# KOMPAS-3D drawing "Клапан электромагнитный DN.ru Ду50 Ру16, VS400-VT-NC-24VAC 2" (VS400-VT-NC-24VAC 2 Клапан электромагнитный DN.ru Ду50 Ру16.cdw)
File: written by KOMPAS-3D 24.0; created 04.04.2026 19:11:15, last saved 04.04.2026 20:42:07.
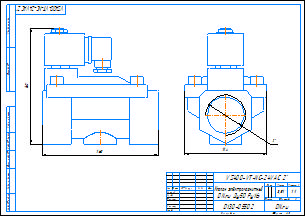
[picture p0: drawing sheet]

Document properties: c3d_UniqueCompID: ef56311e-7521-43dc-8291-0e6108b3d81d; Обозначение: VS400-ET-NC-220VAC 2; Наименование: Клапан электромагнитный DN.ru Ду50 Ру16; Автор: artio; Класс точности: c; Знак неуказанной шероховатости: Шероховатость не задана; Рассекать на разрезах: Да; c3d_UniqueCompID: ef56311e-7521-43dc-8291-0e6108b3d81d; Обозначение: VS400-ET-NC-220VAC 1; Наименование: Клапан электромагнитный DN.ru Ду25 Ру16; Автор: artio; Класс точности: c; Знак неуказанной шероховатости: Шероховатость не задана; Рассекать на разрезах: Да; c3d_UniqueCompID: ef56311e-7521-43dc-8291-0e6108b3d81d; Обозначение: VS400-ET-NC-220VAC 1-2; Наименование: Клапан электромагнитный DN.ru Ду15 Ру16; Автор: artio; Класс точности: c; Знак неуказанной шероховатости: Шероховатость не задана; Рассекать на разрезах: Да; c3d_UniqueCompID: ef56311e-7521-43dc-8291-0e6108b3d81d; Обозначение: VS400-ET-NC-220VAC 3-4; Наименование: Клапан электромагнитный DN.ru Ду20 Ру16; Автор: artio; Класс точности: c; Знак неуказанной шероховатости: Шероховатость не задана; Рассекать на разрезах: Да; c3d_UniqueCompID: ef56311e-7521-43dc-8291-0e6108b3d81d; Обозначение: VS400-ET-NC-220VAC 1 1-4; Наименование: Клапан электромагнитный DN.ru Ду32 Ру16; Автор: artio; Класс точности: c; Знак неуказанной шероховатости: Шероховатость не задана; Рассекать на разрезах: Да; c3d_UniqueCompID: ef56311e-7521-43dc-8291-0e6108b3d81d; Обозначение: VS400-ET-NC-220VAC 3-8; Наименование: Клапан электромагнитный DN.ru Ду10 Ру16; Автор: artio; Класс точности: c; Знак неуказанной шероховатости: Шероховатость не задана; Рассекать на разрезах: Да; c3d_UniqueCompID: ef56311e-7521-43dc-8291-0e6108b3d81d; Обозначение: VS400-ET-NC-220VAC 1 1-2; Наименование: Клапан электромагнитный DN.ru Ду40 Ру16; Автор: artio; Класс точности: c; Знак неуказанной шероховатости: Шероховатость не задана; Рассекать на разрезах: Да; Автор: artio; Форматы листов документа: A3; Полное имя файла: VS400-VT-NC-24VAC 2 Клапан электромагнитный DN.ru Ду50 Ру16.m3d; Масса: 3.509; Наименование: Клапан электромагнитный DN.ru Ду50 Ру16; Количество листов документа: 1; Примечание: D130-05502

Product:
- Body: Тело 1  | qty 1
    Масса: 7.119215
- Part/product: Клапан электромагнитный DN.ru Ду50 Ру16  | designation VS400-VT-NC-24VAC 2
    Масса: 3.509
    Раздел спецификации: Прочие изделия
    Примечание: D130-05502
    additional columns: ef56311e-7521-43dc-8291-0e6108b3d81d; VS400-ET-NC-220VAC 2; artio; c; Шероховатость не задана; Да

Views: Вид 1, Спереди
Referenced files in C:\Users\artio\OneDrive\Рабочий стол\Клапан электромагнитный DN.ru\VS400-ET-NC\VS400-ET-NC-24VDC\: VS400-ET-NC-24VDC 3-8 Клапан электромагнитный DN.ru Ду10 Ру16.m3d
Referenced files in C:\Users\artio\OneDrive\Рабочий стол\Клапан электромагнитный DN.ru\VS400-VT-NC\VS400-VT-NC-24VAC\: VS400-VT-NC-24VAC 2 Клапан электромагнитный DN.ru Ду50 Ру16.m3d
Referenced files in C:\Users\artio\OneDrive\Рабочий стол\Клапан электромагнитный DN.ru\VS400-ET-NC\: VS400-ET-NC-24VDC 3-8 Клапан электромагнитный DN.ru Ду10 Ру16.cdw
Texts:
  VS400-VT-NC-24VAC 2
  Клапан электромагнитный
  DN.ru Ду50 Ру16
  VS400-VT-NC-24VAC 2"
  VS400-VT-NC-24VAC 2"-
  Клапан электромагнитный DN.ru Ду50 Ру16
  VS400-VT-NC-24VAC 2 Клапан электромагнитный DN.ru Ду50 Ру16
Dimensions and other numbers on the sheet: 0; 3; 2; 4; 114; 1:1; 1; 3,51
